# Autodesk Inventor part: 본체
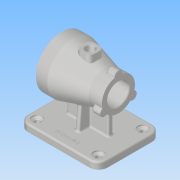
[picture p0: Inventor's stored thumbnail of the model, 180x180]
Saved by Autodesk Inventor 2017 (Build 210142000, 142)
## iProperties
Part Number: 본체
Material: 알루미늄 6061
Document SubType Name: Modeling
Designer: user
Density: 2.7 g/cm^3
Appearance: 알루미늄 - 평지
Mass: 1218.8 g
Surface Area: 896.758 cm^2
Volume: 451.408 cm^3
Author: user
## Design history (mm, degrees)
sketch "스케치1"
  geometry: L1 (70, 55)-(-70, 55); L2 (-70, 55)-(-70, -55); L3 (-70, -55)-(70, -55); L4 (70, -55)-(70, 55); L5 (70, 55)-(-70, -55); L6 (-70, 55)-(70, -55); 1 further point
  constraints: 12 end point, 2 midpoint, 2 parallel, 1 horizontal, 1 perpendicular
  dimensions: "d0" = 110 distance of L3.end L1.start; "d1" = 140 distance of L1.start L1.end
extrude "돌출1" new body sketch "스케치1" distance "d2" = 12; taper "d3" = 0 deg
sketch "스케치2"
  geometry: L1 (70, 55)-(-70, 55) reference; L2 (-70, 55)-(-70, -55) reference; 5 further points
  constraints: 2 horizontal alignment, 2 vertical alignment
  dimensions: "d4" = 108 distance of point (54, 39) point (-54, 39); "d5" = 16 distance from line of L2 point (-54, 39); "d6" = 16 distance from line of L1 point (-54, 39); "d7" = 78 distance of point (-54, 39) point (-54, -39)
hole "구멍1" sketch "스케치2" at (-54, 39), (-54, -39), (54, -39), (54, 39) diameter "d8" = 18; stored, may be unused: countersink angle "d12" = 90 deg, drill point angle "d14" = 118 deg; dims "d9" = 6, "d10" = 4, "d11" = 2, "d13" = 2
sketch "스케치3"
  geometry: C1 r 9 at (54, -39) reference; C2 r 9 at (-54, 39) reference; C3 r 9 at (-54, -39) reference; C4 r 9 at (54, 39) reference; 5 further points
  constraints: 4 coincident
hole "구멍2" sketch "스케치3" at (-54, 39), (-54, -39), (54, -39), (54, 39) diameter "d15" = 9; stored, may be unused: countersink angle "d19" = 90 deg, drill point angle "d21" = 118 deg; dims "d16" = 6, "d17" = 4, "d18" = 2, "d20" = 2
sketch "스케치4"
  geometry: L1 (-50, 82)-(50, 82); L2 (50, 82)-(50, 111); L3 (50, 111)-(27, 111); L4 (27, 111)-(-30, 127); L5 (-30, 127)-(-50, 127); L6 (-50, 127)-(-50, 82); L7 (-70, 0)-(70, 0) reference; 3 further points
  constraints: 12 end point, 3 perpendicular, 2 horizontal, 2 midpoint, 1 vertical alignment
  dimensions: "d22" = 82 distance between parallel lines of L1 L7; "d23" = 90 diameter of L5 L1; "d24" = 58 diameter of L3 L1; "d25" = 100 distance of L1.start L1.end; "d26" = 20 distance of L4.end L5.end; "d27" = 23 distance of L2.end L3.end
revolve "회전1" sketch "스케치4" stored, may be unused: angle "d28" = 90 deg
sketch "스케치6"
  geometry: L1 (-37, 70)-(37, 70); L2 (37, 70)-(37, 0); L3 (37, 0)-(-37, 0); L4 (-37, 0)-(-37, 70); L5 (70, 0)-(-70, 0) reference; 2 further points
  constraints: 8 end point, 2 parallel, 1 coincident, 1 collinear, 1 horizontal, 1 midpoint, 1 perpendicular
  dimensions: "d33" = 74 distance of L2.end L3.end; "d34" = 70 distance of L1.end L2.end
extrude "돌출3" join sketch "스케치6" stored distance "d35" = 8; taper "d36" = 0 deg
sketch "스케치7"
  geometry: L1 (60, 18.751)-(0, 24); L2 (0, 24)-(0, -24); L3 (0, -24)-(60, -18.751); L4 (60, -18.751)-(60, 18.751); L5 (0, -55)-(0, 55) reference; L6 (12, -55)-(12, 55) reference; 3 further points
  constraints: 8 end point, 2 midpoint, 1 coincident, 1 collinear, 1 parallel
  dimensions: "d37" = 95 deg angle of L3 L6; "d38" = 95 deg angle of L1 L6; "d39" = 24 distance of L1.end point (0, 0); "d40" = 60 distance between parallel lines of L2 L4; "d101" = 24 distance of L2.end point (0, 0) (derived)
extrude "돌출4" join sketch "스케치7" stored distance "d41" = 8; taper "d42" = 0 deg
sketch "스케치8"
  geometry: L1 (-50, 37)-(-50, 127) reference; L2 (-50, 82)-(50, 82); L3 (50, 82)-(50, 101); L4 (50, 53)-(50, 111) reference; L5 (20, 101)-(20, 107); L6 (20, 107)-(-27, 107); L7 (-27, 107)-(-27, 113); L8 (-27, 113)-(-50, 113); L9 (-50, 113)-(-50, 82); L10 (20, 101)-(50, 101); L11 (70, 0)-(-70, 0) reference; 1 further point
  constraints: 16 end point, 4 perpendicular, 2 horizontal, 1 collinear, 1 midpoint, 1 point on line, 1 vertical
  dimensions: "d43" = 62 diameter of L8 L2; "d44" = 50 diameter of L6 L2; "d45" = 38 diameter of L10 L2; "d46" = 23 distance of L7.end L8.end; "d47" = 30 distance of L5.start L3.end; "d48" = 82 distance between parallel lines of L11 L2
revolve "회전2" sketch "스케치8" stored, may be unused: angle "d49" = 90 deg
sketch "스케치9"
  geometry: L1 (0, 0)-(0, 29); L2 (0, 0)-(-25.115, -14.5); L3 (0, 0)-(25.115, -14.5); C1 r 7 at (-25.115, -14.5); C2 r 7 at (0, 29); C3 r 7 at (25.115, -14.5); A1 r 29 centre (0, 0) between (0, 29) and (-25.115, -14.5) reference; 1 further point
  constraints: 6 end point, 3 centre point, 3 coincident, 3 point on circle, 1 vertical
  dimensions: "d50" = 120 deg angle of L2 L1; "d51" = 120 deg angle of L1 L3; "d52" = 14 diameter of C1; "d53" = 14 diameter of C2; "d54" = 14 diameter of C3
extrude "돌출5" join sketch "스케치9" distance "d55" = 15; taper "d56" = 0 deg
node "작업 평면1"
sketch "스케치10"
  geometry: L1 (12.5, 12.5)-(-12.5, 12.5); L2 (-12.5, 12.5)-(-12.5, -12.5); L3 (-12.5, -12.5)-(12.5, -12.5); L4 (12.5, -12.5)-(12.5, 12.5); L5 (12.5, 12.5)-(-12.5, -12.5); L6 (-12.5, 12.5)-(12.5, -12.5); 1 further point
  constraints: 12 end point, 2 midpoint, 2 parallel, 1 horizontal, 1 perpendicular
  dimensions: "d58" = 25 distance of L3.end L2.end; "d59" = 25 distance of L2.end L1.end
extrude "돌출6" join sketch "스케치10" stored distance "d60" = 15; taper "d61" = 0 deg
sketch "스케치11"
  geometry: C1 r 7.5 at (0, 0); 1 further point
  constraints: 1 centre point, 1 coincident
  dimensions: "d62" = 15 diameter of C1
extrude "돌출7" cut sketch "스케치11" distance "d63" = 50; taper "d64" = 0 deg
sketch "스케치12"
  geometry: L1 (0, 0)-(0, 40); L2 (-34.641, 20)-(0, 0); L3 (-34.641, -20)-(0, 0); L4 (0, -40)-(0, 0); L5 (34.641, -20)-(0, 0); L6 (34.641, 20)-(0, 0); C1 r 31 at (0, 0) reference; A1 r 40 centre (0, 0) between (0, 40) and (-34.641, 20); 1 further point
  constraints: 12 end point, 6 point on circle, 2 vertical, 1 centre point, 1 coincident
  dimensions: "d65" = 80 diameter of A1; "d66" = 60 deg angle of L1 L2; "d67" = 60 deg angle of L3 L2; "d68" = 60 deg angle of L5 L4; "d69" = 60 deg angle of L6 L5
hole "구멍3" sketch "스케치12" at (0, 40), (-34.641, 20), (-34.641, -20), (0, -40), (34.641, -20), (34.641, 20) diameter "d70" = 3.242; stored, may be unused: countersink angle "d74" = 90 deg, drill point angle "d76" = 118 deg; dims "d71" = 9, "d72" = 4, "d73" = 2, "d75" = 11
sketch "스케치13"
  geometry: A1 r 7 centre (0, 0) between (6.949, -0.845) and (-6.949, -0.845) reference; A2 r 7 centre (-25.115, -43.5) between (-27.858, -37.06) and (-20.909, -49.095) reference; A3 r 7 centre (25.115, -43.5) between (20.909, -49.095) and (27.858, -37.06) reference; A4 r 29 centre (0, -29) between (4, -57.723) and (-4, -57.723) reference; 4 further points
  constraints: 3 coincident
hole "구멍4" sketch "스케치13" at (0, 0), (-25.115, -43.5), (25.115, -43.5) diameter "d77" = 3.242; stored, may be unused: countersink angle "d81" = 90 deg, drill point angle "d83" = 118 deg; dims "d78" = 9, "d79" = 4, "d80" = 2, "d82" = 11
fillet "모깎기1" dims "d84" = 3
fillet "모깎기3" dims "d86" = 8, "d87" = 1
chamfer "모따기1" distance "d88" = 1; stored, may be unused: second distance "d89" = 2, angle "d90" = 45 deg
fillet "모깎기4" dims "d91" = 3
fillet "모깎기5" dims "d92" = 3
fillet "모깎기6" dims "d93" = 1, "d94" = 3
fillet "모깎기7" dims "d95" = 16
node "작업 평면2"
sketch "스케치14"
  geometry: L1 (-54, -55)-(54, -55) reference; 2 further points
  constraints: 1 vertical alignment, 1 other
  dimensions: "d97" = 15 distance from line of point (0, -40) L1
feature "엠보싱1" sketch "스케치14" dims "d0" = 110, "d1" = 140, "d98" = 0.5, "d99" = 0
fillet "모깎기8" dims "d100" = 1
node "솔리드1"
other parameters: "d57" = 127, "d96" = 5
